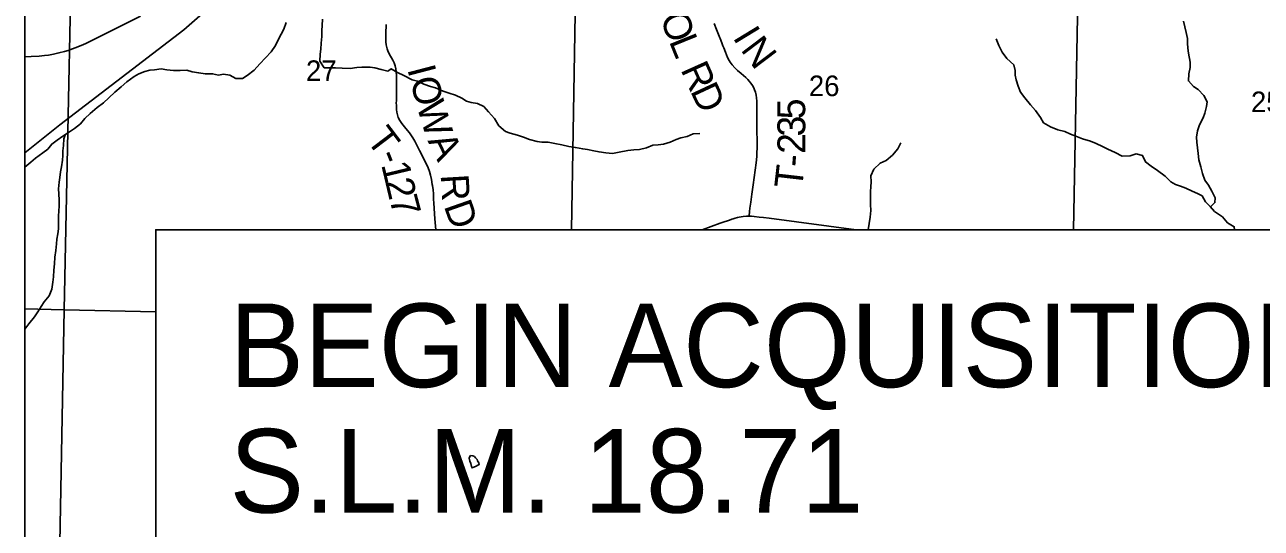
# Model space of a CAD drawing. Extents: x 0 to 34, y 0 to 22.
# Drawn here: x 1.631 to 4.145, y 16.751 to 17.774 of the extents above; entities that cross this region are included whole.
import ezdxf

# ---------------------------------------------------------------- set-up
doc = ezdxf.new("R2010")
doc.units = 0
for name, color, linetype in [('GM_X_Corporation', 7, 'Continuous'), ('GM_X_County_Road', 7, 'Continuous'), ('GM_X_Minor_Lake', 7, 'Continuous'), ('GM_X_Minor_River', 7, 'Continuous'), ('GM_X_Rail_Line', 7, 'Continuous'), ('GM_X_Section_Text', 7, 'Continuous'), ('GM_X_State_Route', 7, 'Continuous'), ('GM_X_Township_Road', 7, 'Continuous'), ('GM_X_Township_Road_Text', 7, 'Continuous'), ('SH_Data', 7, 'Continuous'), ('SH_Text', 7, 'Continuous')]:
    doc.layers.add(name, color=color, linetype=linetype)

msp = doc.modelspace()

# ---------------------------------------------------------------- linework, layer by layer
at = {"layer": 'GM_X_Corporation'}
for points in [[(8.4311, 21.3734), (1.6311, 21.3734), (1.6311, 16.1731), (2.3716, 16.1532), (2.3935, 16.1523), (3.7652, 16.1115), (4.1576, 16.1007)], [(4.7823, 18.128), (4.0508, 18.1454), (3.7812, 18.1547), (3.7776, 18.3354), (3.7807, 18.4204), (3.7875, 18.9248), (3.7889, 19.1658), (3.7877, 19.187), (3.1142, 19.2057), (2.7749, 19.2162), (2.7798, 20.0198), (2.7831, 20.242), (2.7976, 21.3075), (2.7987, 21.3734), (1.6311, 21.3734), (1.6311, 16.1731), (2.3716, 16.1532), (2.3935, 16.1523), (3.7652, 16.1115), (4.1576, 16.1007)], [(1.8974, 17.1907), (1.7115, 17.1949), (1.7326, 18.216), (2.7572, 18.1961), (2.7424, 17.3579)], [(2.7424, 17.3579), (2.7572, 18.1961), (3.7781, 18.1522), (3.763, 17.3579)], [(3.763, 17.3579), (3.7781, 18.1522), (4.7872, 18.1255), (4.7868, 18.1081), (4.7707, 17.1031), (4.5509, 17.1099)], [(2.7241, 16.6637), (2.7088, 16.1431), (1.7396, 16.1729), (1.6922, 16.1742), (1.7115, 17.1949), (1.8974, 17.1907)]]:
    msp.add_lwpolyline(points, dxfattribs=at)
for points in [[(1.6311, 18.2188), (1.6311, 17.1972), (1.7115, 17.1949), (1.7326, 18.216)], [(1.6311, 17.1972), (1.6311, 16.1758), (1.6922, 16.1742), (1.7115, 17.1949)]]:
    msp.add_lwpolyline(points, close=True, dxfattribs=at)
at = {"layer": 'GM_X_County_Road'}
for points in [[(3.0084, 17.3579), (3.045, 17.3709), (3.0491, 17.3724), (3.0638, 17.3774), (3.069, 17.3792), (3.0717, 17.3802), (3.0752, 17.3814), (3.08, 17.3825), (3.0836, 17.3833), (3.0916, 17.3846), (3.0984, 17.3852), (3.1035, 17.3853)], [(3.1035, 17.3853), (3.109, 17.3852), (3.1139, 17.3847), (3.1244, 17.3835), (3.133, 17.3826), (3.1448, 17.3813), (3.3215, 17.3579)]]:
    msp.add_lwpolyline(points, dxfattribs=at)
at = {"layer": 'GM_X_Minor_Lake'}
for points in [[(2.551, 16.8909), (2.5476, 16.8943), (2.5453, 16.8973), (2.5419, 16.8984), (2.5377, 16.8988), (2.5362, 16.8969), (2.5347, 16.8934), (2.5363, 16.8874), (2.5382, 16.8828), (2.5394, 16.8768), (2.5405, 16.8738), (2.5489, 16.8776)], [(2.5489, 16.8776), (2.5526, 16.8795), (2.5549, 16.8807), (2.5541, 16.8841), (2.5518, 16.8879), (2.551, 16.8909)]]:
    msp.add_lwpolyline(points, dxfattribs=at)
at = {"layer": 'GM_X_Minor_River'}
for points in [[(2.1625, 17.7787), (2.1581, 17.7654), (2.1525, 17.7555), (2.1455, 17.7422), (2.1407, 17.7323), (2.1321, 17.7197), (2.1205, 17.707), (2.1093, 17.6952), (2.0973, 17.6822), (2.0834, 17.6714), (2.0736, 17.6652), (2.06, 17.6655), (2.0478, 17.6722), (2.0349, 17.6739), (2.0251, 17.6723), (2.0129, 17.6748), (1.9982, 17.675), (1.9849, 17.6764), (1.9713, 17.6789), (1.961, 17.6819), (1.9474, 17.6817), (1.9334, 17.6812), (1.9201, 17.6829), (1.9084, 17.6851), (1.8952, 17.6831), (1.8853, 17.6818), (1.8755, 17.6791), (1.8634, 17.6748), (1.8533, 17.669), (1.839, 17.6586), (1.8274, 17.6482), (1.8143, 17.6371), (1.8019, 17.626), (1.791, 17.616), (1.7782, 17.6064), (1.7644, 17.5941), (1.7535, 17.5838), (1.7445, 17.5731), (1.7321, 17.5638), (1.7182, 17.5542), (1.7084, 17.5477), (1.6972, 17.54), (1.6859, 17.5319), (1.6781, 17.5216), (1.6679, 17.5139), (1.6533, 17.5031), (1.6435, 17.4954), (1.6311, 17.4852)], [(2.3713, 17.6812), (2.369, 17.6804), (2.3558, 17.6837), (2.3429, 17.6866), (2.3334, 17.688), (2.3164, 17.6879), (2.3061, 17.6874), (2.2925, 17.6857), (2.2766, 17.6859), (2.2626, 17.6869), (2.2528, 17.6868), (2.2399, 17.6871), (2.2311, 17.7006), (2.2317, 17.7146), (2.2331, 17.7249), (2.2341, 17.737), (2.2351, 17.7507), (2.2354, 17.7628), (2.236, 17.7727), (2.2366, 17.7856)], [(4.0416, 17.4046), (4.0508, 17.413), (4.0515, 17.4225), (4.0446, 17.4364), (4.0377, 17.4485), (4.0304, 17.4583), (4.0258, 17.4723), (4.0222, 17.486), (4.0184, 17.5), (4.0171, 17.5129), (4.0155, 17.5246), (4.0139, 17.536), (4.0135, 17.5458), (4.0157, 17.5591), (4.0197, 17.5713), (4.0268, 17.585), (4.0306, 17.5946), (4.0335, 17.6086), (4.0353, 17.6181), (4.028, 17.6306), (4.017, 17.6426), (4.0071, 17.649), (3.9971, 17.6603), (3.9981, 17.6747), (4.0003, 17.6873), (4.0003, 17.6987), (3.9971, 17.7165), (3.9959, 17.7271), (3.995, 17.7373), (3.995, 17.7468), (3.9922, 17.7586), (3.9895, 17.7699), (3.9871, 17.782)], [(3.6756, 17.6114), (3.6641, 17.6258), (3.6553, 17.6371), (3.6507, 17.6499), (3.6468, 17.6624), (3.6448, 17.6719), (3.6448, 17.6814), (3.642, 17.6931), (3.6275, 17.7059), (3.618, 17.7187), (3.6118, 17.732), (3.6064, 17.746)], [(2.3713, 17.6812), (2.3759, 17.6849), (2.3888, 17.6774), (2.4021, 17.6714), (2.4185, 17.6624), (2.4295, 17.6595), (2.4428, 17.6539), (2.4561, 17.6487), (2.466, 17.6465), (2.4816, 17.6394), (2.4941, 17.6353), (2.5071, 17.6313), (2.52, 17.6249), (2.5295, 17.6193), (2.539, 17.6167), (2.5519, 17.6146), (2.5645, 17.6086), (2.5737, 17.5973), (2.5863, 17.5841), (2.5947, 17.569), (2.6084, 17.5577), (2.6183, 17.554), (2.6328, 17.5499), (2.6449, 17.5459), (2.6575, 17.541), (2.6727, 17.537), (2.6821, 17.5359), (2.695, 17.536), (2.7087, 17.5331), (2.7231, 17.5302), (2.7372, 17.5273), (2.7508, 17.5247), (2.7656, 17.5222), (2.7755, 17.5207), (2.788, 17.5182), (2.7987, 17.516), (2.8127, 17.5138), (2.8264, 17.5128), (2.8396, 17.5152), (2.857, 17.5187), (2.8695, 17.52), (2.8809, 17.5208), (2.8949, 17.5243), (2.9081, 17.5294), (2.9187, 17.5302), (2.9301, 17.5318), (2.943, 17.5361), (2.9554, 17.5415), (2.9653, 17.5443), (2.9778, 17.5474), (2.9899, 17.5528), (3.0035, 17.5537)], [(4.0905, 17.3579), (4.0902, 17.3639), (4.0765, 17.3722), (4.0662, 17.3839), (4.0502, 17.3947), (4.041, 17.4053), (4.0315, 17.4143), (4.0246, 17.4264), (4.0151, 17.4313), (4.0048, 17.4365), (3.9919, 17.4421), (3.9808, 17.4465), (3.9706, 17.4499), (3.9611, 17.4551), (3.95, 17.4664), (3.9344, 17.4781), (3.921, 17.4867), (3.9096, 17.4957), (3.9038, 17.5085), (3.8909, 17.5119), (3.8784, 17.508), (3.8625, 17.5071), (3.8477, 17.5149), (3.8332, 17.5216), (3.8222, 17.5272), (3.8092, 17.5332), (3.7982, 17.5377), (3.7819, 17.5429), (3.7682, 17.5477), (3.7575, 17.5521), (3.7454, 17.5574), (3.7317, 17.561), (3.7165, 17.567), (3.7024, 17.5752), (3.6963, 17.5862), (3.6859, 17.6001), (3.6756, 17.6114)], [(1.7131, 17.5508), (1.7104, 17.5424), (1.7098, 17.5287), (1.7087, 17.5185), (1.7085, 17.509), (1.7078, 17.4995), (1.7061, 17.4859), (1.7039, 17.4752), (1.7025, 17.4642), (1.7011, 17.4547), (1.7001, 17.4411), (1.7006, 17.4305), (1.7011, 17.4176), (1.7008, 17.4058), (1.7005, 17.396), (1.6999, 17.3857), (1.6996, 17.3762), (1.6998, 17.3599), (1.6984, 17.3493), (1.6966, 17.3387), (1.6956, 17.3292), (1.6942, 17.3155), (1.6924, 17.3022), (1.6918, 17.2886), (1.6904, 17.2757), (1.6898, 17.2624), (1.6884, 17.251), (1.6859, 17.237), (1.6811, 17.2233), (1.6707, 17.211), (1.6643, 17.2015), (1.658, 17.1912), (1.6509, 17.1805), (1.6397, 17.1664), (1.6315, 17.156), (1.6311, 17.1555)], [(3.3459, 17.3579), (3.3497, 17.3834), (3.3511, 17.3971), (3.3506, 17.4092), (3.3505, 17.4229), (3.3508, 17.4354), (3.3511, 17.4449), (3.3522, 17.4555), (3.3514, 17.4677), (3.3573, 17.481), (3.3705, 17.4929), (3.3822, 17.4983), (3.3954, 17.5094), (3.4063, 17.5224), (3.4123, 17.5342)]]:
    msp.add_lwpolyline(points, dxfattribs=at)
at = {"layer": 'GM_X_Rail_Line'}
msp.add_lwpolyline([(4.1788, 20.304), (4.0429, 20.1945), (3.3384, 19.6119), (3.2847, 19.5633), (3.2446, 19.5253), (3.2015, 19.4768), (3.1607, 19.4315), (3.1275, 19.3905), (3.0936, 19.3436), (2.5732, 18.599), (2.0707, 17.885), (2.0334, 17.8382), (1.9924, 17.7972), (1.9547, 17.7644), (1.7027, 17.5707), (1.6311, 17.5139)], dxfattribs=at)
at = {"layer": 'GM_X_State_Route'}
for points in [[(1.7553, 17.7366), (1.7688, 17.7429), (1.7894, 17.7531), (1.8665, 17.7918)], [(1.6311, 17.7091), (1.6442, 17.7096), (1.6603, 17.7107), (1.6714, 17.7118), (1.6794, 17.7128), (1.6897, 17.7147), (1.7006, 17.7171), (1.712, 17.7201), (1.7197, 17.7224), (1.7284, 17.7254), (1.7394, 17.7296), (1.7508, 17.7346), (1.7553, 17.7366)]]:
    msp.add_lwpolyline(points, dxfattribs=at)
at = {"layer": 'GM_X_Township_Road'}
for points in [[(2.4668, 17.3579), (2.4646, 17.3802), (2.4628, 17.4117), (2.4624, 17.42), (2.4625, 17.4238), (2.4623, 17.4268), (2.4621, 17.4311), (2.4613, 17.439), (2.46, 17.4476), (2.4596, 17.4501), (2.458, 17.4598), (2.4561, 17.4689), (2.4541, 17.4761), (2.4513, 17.4836), (2.4484, 17.4897), (2.4419, 17.5024), (2.4388, 17.5084), (2.4336, 17.5189), (2.4317, 17.5228), (2.4285, 17.5295), (2.4244, 17.5377), (2.4204, 17.5446), (2.4162, 17.5507), (2.4132, 17.5547), (2.4062, 17.5634), (2.3981, 17.5735), (2.3938, 17.5796), (2.3906, 17.5856), (2.3887, 17.5914), (2.3876, 17.5968), (2.387, 17.6024), (2.3867, 17.611), (2.3866, 17.6153), (2.3867, 17.6203), (2.3868, 17.624), (2.3869, 17.6283), (2.387, 17.632), (2.387, 17.6351), (2.387, 17.6376), (2.3871, 17.6413), (2.387, 17.6437), (2.387, 17.6474), (2.3869, 17.6517), (2.3869, 17.6535), (2.3867, 17.6616), (2.3868, 17.6715), (2.3865, 17.6789), (2.3856, 17.6851), (2.3841, 17.6911), (2.3819, 17.6969), (2.3792, 17.7025), (2.3722, 17.715), (2.3693, 17.7211), (2.3679, 17.7252), (2.3671, 17.7282), (2.3661, 17.7337), (2.3656, 17.7399), (2.3654, 17.7486), (2.3656, 17.7567), (2.3658, 17.7747)], [(3.1035, 17.3853), (3.1044, 17.3921), (3.1047, 17.3946), (3.1055, 17.4014), (3.1073, 17.4136), (3.1096, 17.4303), (3.112, 17.4494), (3.1179, 17.4937), (3.1193, 17.5067), (3.1198, 17.5141), (3.1202, 17.524), (3.1202, 17.5327), (3.1201, 17.5408), (3.1198, 17.5569), (3.1197, 17.5675), (3.1195, 17.5774), (3.1194, 17.5936), (3.1194, 17.6073), (3.1193, 17.6191), (3.1188, 17.6259), (3.1181, 17.6314), (3.1165, 17.6374), (3.1149, 17.6421), (3.1131, 17.6461), (3.1104, 17.651), (3.1074, 17.6557), (3.1039, 17.66), (3.1009, 17.6632), (3.0969, 17.6671), (3.0874, 17.6751), (3.0799, 17.6817), (3.0746, 17.6869), (3.0694, 17.693), (3.0653, 17.6985), (3.0634, 17.7017), (3.0599, 17.7082), (3.0556, 17.7186), (3.0524, 17.7273), (3.0506, 17.7319), (3.0493, 17.7354), (3.0463, 17.7429), (3.0432, 17.751), (3.0403, 17.7578), (3.0375, 17.7647), (3.0326, 17.7768)]]:
    msp.add_lwpolyline(points, dxfattribs=at)
at = {"layer": 'SH_Data'}
msp.add_lwpolyline([(1.8974, 16.6637), (4.5509, 16.6637), (4.5509, 17.3579), (1.8974, 17.3579)], close=True, dxfattribs=at)
at = {"layer": 'SH_Text'}
msp.add_line((1.6311, 14.5734), (1.6311, 21.3734), dxfattribs=at)

# ---------------------------------------------------------------- texts
at = {"layer": 'GM_X_Section_Text'}
for s, p in [('27', (2.2029, 17.6601)), ('26', (3.2253, 17.6293)), ('25', (4.1241, 17.5968))]:
    msp.add_text(s, height=0.04186, rotation=0, dxfattribs=at).set_placement(p)
at = {"layer": 'GM_X_Township_Road_Text'}
for s, rotation, p in [('O', 291.2907, (2.9218, 17.7886)), ('L', 292.0099, (2.9403, 17.7412)), ('I', 301.3208, (3.0696, 17.7487)), ('N', 307.0848, (3.0852, 17.7236)), ('R', 294.1579, (2.9639, 17.6836)), ('I', 284.6554, (2.4086, 17.6846)), ('O', 283.9735, (2.4145, 17.6622)), ('D', 295.0313, (2.9834, 17.6401)), ('W', 286.6871, (2.4273, 17.6109)), ('5', 90.4465, (3.218, 17.5825)), ('T', 307.2211, (2.324, 17.5403)), ('3', 90.3644, (3.2182, 17.5474)), ('2', 89.9892, (3.2182, 17.512)), ('A', 295.745, (2.4498, 17.5387)), ('-', 291.5243, (2.3477, 17.51)), ('-', 85.646, (3.2163, 17.484)), ('1', 283.4335, (2.3556, 17.4903)), ('T', 83.4416, (3.2112, 17.4394)), ('2', 283.2507, (2.3637, 17.4564)), ('R', 273.4367, (2.4766, 17.4694)), ('7', 284.6489, (2.3721, 17.4208)), ('D', 289.3425, (2.4827, 17.4063))]:
    msp.add_text(s, height=0.0568, rotation=rotation, dxfattribs=at).set_placement(p)
at = {"layer": 'SH_Text'}
for s, p in [('BEGIN ACQUISITION', (2.0474, 17.0379)), ('S.L.M. 18.71', (2.0474, 16.7829))]:
    msp.add_text(s, height=0.17, dxfattribs=at).set_placement(p)

doc.saveas('drawing.dxf')
